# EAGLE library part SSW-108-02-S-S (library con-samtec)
THROUGH-HOLE .025" SQ POST SOCKET Source: Samtec SSW.pdf
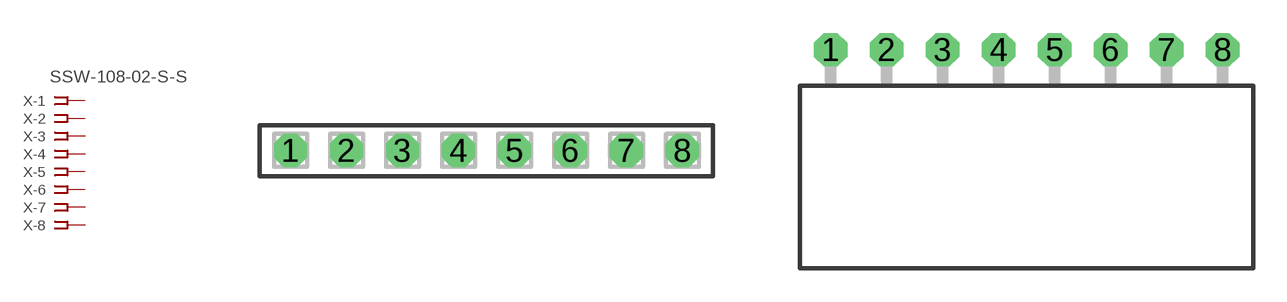
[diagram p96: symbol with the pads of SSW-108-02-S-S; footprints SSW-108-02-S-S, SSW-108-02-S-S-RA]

Designator prefix X; gates -1=FPINV -2=FPIN -3=FPIN -4=FPIN -5=FPIN -6=FPIN -7=FPIN -8=FPIN

## SSW-108-02-S-S (MPN: SSW-108-02-S-S; OC_FARNELL: unknown; OC_NEWARK: 11P9448)  [SSW-108-02-S-S]
1  -1:1  pas
2  -2:1  pas
3  -3:1  pas
4  -4:1  pas
5  -5:1  pas
6  -6:1  pas
7  -7:1  pas
8  -8:1  pas

## SSW-108-02-S-S-RA (MPN: SSW-108-02-S-S-RA; OC_FARNELL: unknown; OC_NEWARK: 11P9449)  [SSW-108-02-S-S-RA]
Pads as for SSW-108-02-S-S

## Footprint SSW-108-02-S-S (pad centres in mm)
THROUGH-HOLE .025" SQ POST SOCKET Source: Samtec SSW.pdf
drill 1 pad 1.5 octagon: 1 -8.89,0; 2 -6.35,0; 3 -3.81,0; 4 -1.27,0; 5 1.27,0; 6 3.81,0; 7 6.35,0; 8 8.89,0

## Footprint SSW-108-02-S-S-RA (pad centres in mm)
THROUGH-HOLE .025" SQ POST SOCKET Source: Samtec SSW.pdf
drill 1 pad 1.5 octagon: 1 -8.89,1.524; 2 -6.35,1.524; 3 -3.81,1.524; 4 -1.27,1.524; 5 1.27,1.524; 6 3.81,1.524; 7 6.35,1.524; 8 8.89,1.524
